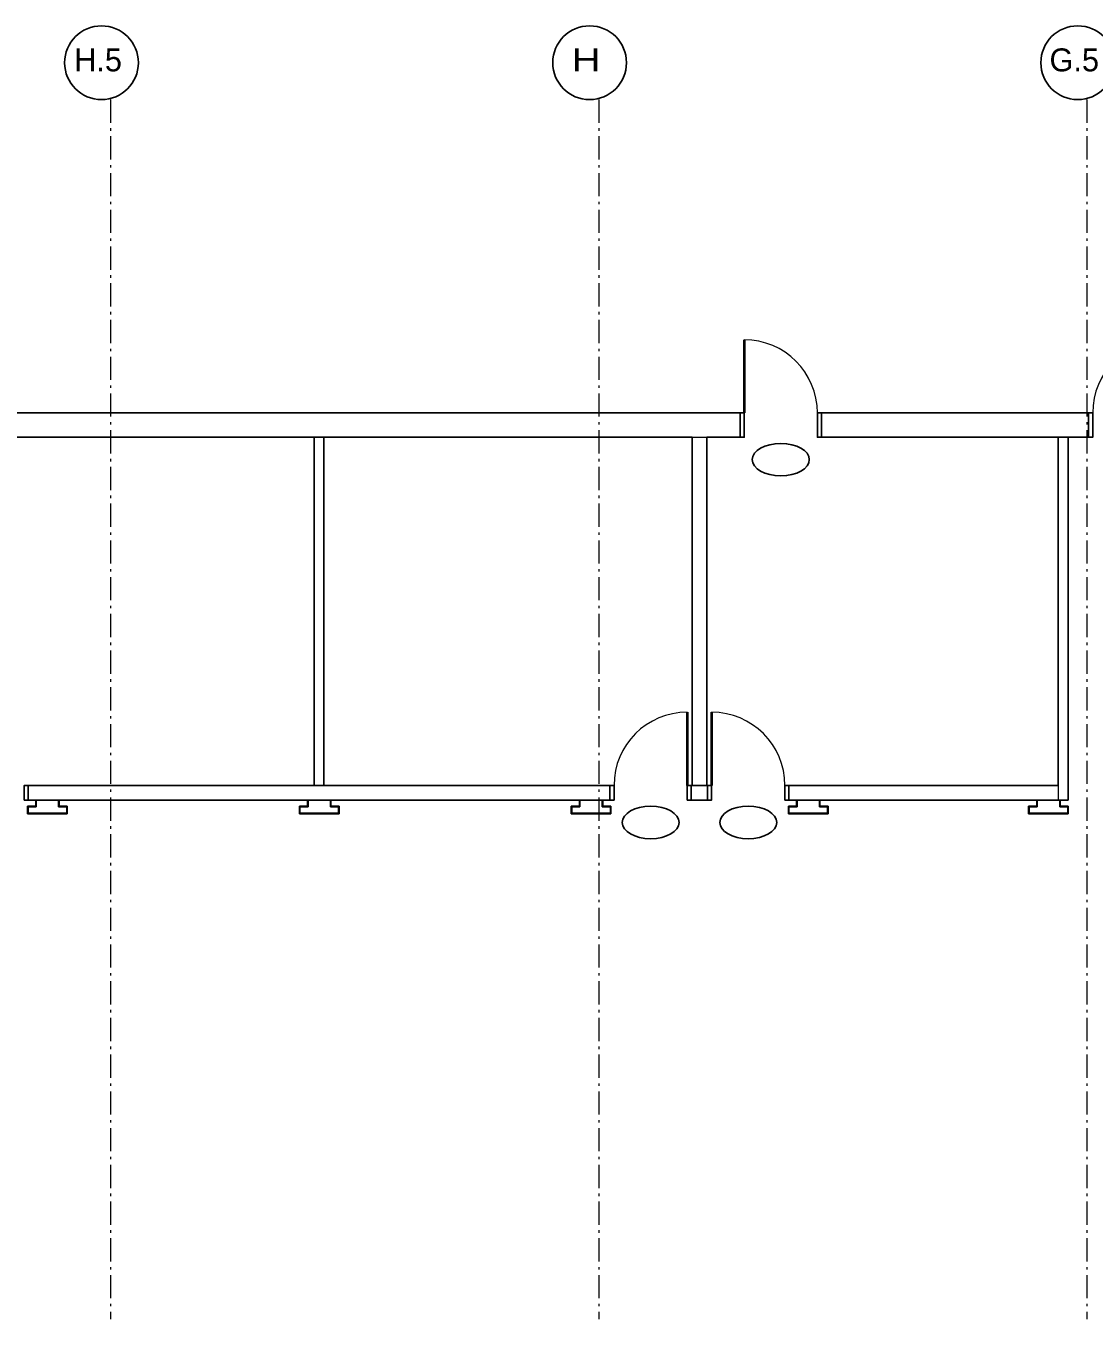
# Model space of a CAD drawing. Extents: x 10076 to 10305, y 10052 to 10157.
# Drawn here: x 10121.1 to 10164.8, y 10104.1 to 10157.1 of the extents above; entities that cross this region are included whole.
import ezdxf
from ezdxf.enums import TextEntityAlignment as Align

# ---------------------------------------------------------------- set-up
doc = ezdxf.new("R2010")
doc.units = 0
doc.header["$LTSCALE"] = 0.19
doc.linetypes.add('DOT_DASHED', pattern=[7.7, 5, -1.2, 0.3, -1.2])
for name, color, linetype, lineweight in [('1', 7, 'Continuous', 13), ('10', 7, 'DOT_DASHED', 13), ('11', 7, 'Continuous', 25), ('23', 7, 'Continuous', 25), ('25', 7, 'Continuous', 13), ('26', 7, 'Continuous', 25), ('42', 7, 'Continuous', 25)]:
    doc.layers.add(name, color=color, linetype=linetype, lineweight=lineweight)

msp = doc.modelspace()

# ---------------------------------------------------------------- linework, layer by layer
at = {"layer": '1'}
for points in [[(10108.9897, 10141.2504), (10108.9897, 10140.2504), (10150.3356, 10140.2504), (10150.3356, 10141.2504)], [(10153.669, 10141.2504), (10153.669, 10140.2504), (10164.6147, 10140.2504), (10164.6147, 10141.2504)], [(10132.8773, 10140.2504), (10132.8773, 10125.9796), (10133.2836, 10125.9796), (10133.2836, 10140.2504)], [(10148.3669, 10125.9796), (10148.3669, 10140.2504), (10148.9711, 10140.2504), (10148.9711, 10125.9796)], [(10163.3669, 10140.2504), (10163.3669, 10125.3754), (10163.7731, 10125.3754), (10163.7731, 10140.2504)], [(10121.169, 10125.9796), (10121.169, 10125.3754), (10145.0023, 10125.3754), (10145.0023, 10125.9796)], [(10148.3356, 10125.3754), (10148.3356, 10125.9796), (10149.0023, 10125.9796), (10149.0023, 10125.3754)], [(10152.3356, 10125.3754), (10152.3356, 10125.9796), (10163.3669, 10125.9796), (10163.3669, 10125.3754)], [(10121.4711, 10125.3754), (10121.4711, 10125.1254), (10121.1377, 10125.1254), (10121.1377, 10124.8129), (10122.7627, 10124.8129), (10122.7627, 10125.1254), (10122.4294, 10125.1254), (10122.4294, 10125.3754)], [(10132.6117, 10125.3754), (10132.6117, 10125.1254), (10132.2784, 10125.1254), (10132.2784, 10124.8129), (10133.9034, 10124.8129), (10133.9034, 10125.1254), (10133.57, 10125.1254), (10133.57, 10125.3754)], [(10143.7523, 10125.3754), (10143.7523, 10125.1254), (10143.419, 10125.1254), (10143.419, 10124.8129), (10145.044, 10124.8129), (10145.044, 10125.1254), (10144.7106, 10125.1254), (10144.7106, 10125.3754)], [(10152.6481, 10125.3754), (10152.6481, 10125.1254), (10152.3148, 10125.1254), (10152.3148, 10124.8129), (10153.9398, 10124.8129), (10153.9398, 10125.1254), (10153.6065, 10125.1254), (10153.6065, 10125.3754)], [(10162.4919, 10125.3754), (10162.4919, 10125.1254), (10162.1586, 10125.1254), (10162.1586, 10124.8129), (10163.7836, 10124.8129), (10163.7836, 10125.1254), (10163.4502, 10125.1254), (10163.4502, 10125.3754)]]:
    msp.add_lwpolyline(points, close=True, dxfattribs=at)
at = {"layer": '10'}
for p, q in [((10124.544, 10154.0964), (10124.544, 10104.0964)), ((10144.544, 10154.0964), (10144.544, 10104.0964)), ((10164.544, 10154.0964), (10164.544, 10104.0964))]:
    msp.add_line(p, q, dxfattribs=at)
at = {"layer": '11'}
for centre in [(10124.169, 10155.6074), (10144.169, 10155.6074), (10164.169, 10155.6074)]:
    msp.add_circle(centre, 1.511, dxfattribs=at)
at = {"layer": '23'}
for p, q in [((10108.9897, 10141.2504), (10150.3356, 10141.2504)), ((10150.3356, 10141.2504), (10150.3356, 10140.2504)), ((10153.669, 10141.2504), (10164.6147, 10141.2504)), ((10153.669, 10141.2504), (10153.669, 10140.2504)), ((10164.6147, 10141.2504), (10164.6147, 10140.2504)), ((10117.794, 10140.2504), (10132.8773, 10140.2504)), ((10132.8773, 10140.2504), (10132.8773, 10125.9796)), ((10133.2836, 10140.2504), (10133.2836, 10125.9796)), ((10133.2836, 10140.2504), (10148.3669, 10140.2504)), ((10148.3669, 10140.2504), (10148.3669, 10125.9796)), ((10148.9711, 10140.2504), (10148.9711, 10125.9796)), ((10148.9711, 10140.2504), (10150.3356, 10140.2504)), ((10153.669, 10140.2504), (10163.3669, 10140.2504)), ((10163.3669, 10140.2504), (10163.3669, 10125.9796)), ((10163.7731, 10140.2504), (10163.7731, 10125.3754)), ((10163.7731, 10140.2504), (10164.6147, 10140.2504)), ((10121.169, 10125.9796), (10132.8773, 10125.9796)), ((10121.169, 10125.9796), (10121.169, 10125.3754)), ((10133.2836, 10125.9796), (10145.0023, 10125.9796)), ((10145.0023, 10125.9796), (10145.0023, 10125.3754)), ((10148.3356, 10125.9796), (10148.3669, 10125.9796)), ((10148.3356, 10125.9796), (10148.3356, 10125.3754)), ((10148.3356, 10125.9796), (10149.0023, 10125.9796)), ((10148.9711, 10125.9796), (10149.0023, 10125.9796)), ((10149.0023, 10125.9796), (10149.0023, 10125.3754)), ((10152.3356, 10125.9796), (10152.3356, 10125.3754)), ((10152.3356, 10125.9796), (10163.3669, 10125.9796)), ((10121.4711, 10125.1254), (10121.1377, 10125.1254)), ((10121.1377, 10125.1254), (10121.1377, 10124.8129)), ((10121.4919, 10125.1046), (10121.1586, 10125.1046)), ((10121.1586, 10125.1046), (10121.1586, 10124.8337)), ((10121.169, 10125.3754), (10121.4711, 10125.3754)), ((10121.4711, 10125.3754), (10121.4711, 10125.1254)), ((10121.4919, 10125.3754), (10121.4919, 10125.1046)), ((10121.4919, 10125.3754), (10122.4086, 10125.3754)), ((10122.4086, 10125.1046), (10122.4086, 10125.3754)), ((10122.7419, 10125.1046), (10122.4086, 10125.1046)), ((10122.4294, 10125.1254), (10122.4294, 10125.3754)), ((10122.4294, 10125.3754), (10132.6117, 10125.3754)), ((10122.7627, 10125.1254), (10122.4294, 10125.1254)), ((10122.7419, 10124.8337), (10122.7419, 10125.1046)), ((10122.7627, 10124.8129), (10122.7627, 10125.1254)), ((10132.6117, 10125.1254), (10132.2784, 10125.1254)), ((10132.2784, 10125.1254), (10132.2784, 10124.8129)), ((10132.6325, 10125.1046), (10132.2992, 10125.1046)), ((10132.2992, 10125.1046), (10132.2992, 10124.8337)), ((10132.6117, 10125.3754), (10132.6117, 10125.1254)), ((10132.6325, 10125.3754), (10132.6325, 10125.1046)), ((10132.6325, 10125.3754), (10133.5492, 10125.3754)), ((10133.5492, 10125.1046), (10133.5492, 10125.3754)), ((10133.8825, 10125.1046), (10133.5492, 10125.1046)), ((10133.57, 10125.1254), (10133.57, 10125.3754)), ((10133.57, 10125.3754), (10143.7523, 10125.3754)), ((10133.9034, 10125.1254), (10133.57, 10125.1254)), ((10133.8825, 10124.8337), (10133.8825, 10125.1046)), ((10133.9034, 10124.8129), (10133.9034, 10125.1254)), ((10143.7523, 10125.1254), (10143.419, 10125.1254)), ((10143.419, 10125.1254), (10143.419, 10124.8129)), ((10143.7731, 10125.1046), (10143.4398, 10125.1046)), ((10143.4398, 10125.1046), (10143.4398, 10124.8337)), ((10143.7523, 10125.3754), (10143.7523, 10125.1254)), ((10143.7731, 10125.3754), (10143.7731, 10125.1046)), ((10143.7731, 10125.3754), (10144.6898, 10125.3754)), ((10144.6898, 10125.1046), (10144.6898, 10125.3754)), ((10145.0231, 10125.1046), (10144.6898, 10125.1046)), ((10144.7106, 10125.1254), (10144.7106, 10125.3754)), ((10144.7106, 10125.3754), (10145.0023, 10125.3754)), ((10145.044, 10125.1254), (10144.7106, 10125.1254)), ((10145.0231, 10124.8337), (10145.0231, 10125.1046)), ((10145.044, 10124.8129), (10145.044, 10125.1254)), ((10148.3356, 10125.3754), (10149.0023, 10125.3754)), ((10152.6481, 10125.1254), (10152.3148, 10125.1254)), ((10152.3148, 10125.1254), (10152.3148, 10124.8129)), ((10152.3356, 10125.3754), (10152.6481, 10125.3754)), ((10152.669, 10125.1046), (10152.3356, 10125.1046)), ((10152.3356, 10125.1046), (10152.3356, 10124.8337)), ((10152.6481, 10125.3754), (10152.6481, 10125.1254)), ((10152.669, 10125.3754), (10152.669, 10125.1046)), ((10152.669, 10125.3754), (10153.5856, 10125.3754)), ((10153.5856, 10125.1046), (10153.5856, 10125.3754)), ((10153.919, 10125.1046), (10153.5856, 10125.1046)), ((10153.6065, 10125.1254), (10153.6065, 10125.3754)), ((10153.6065, 10125.3754), (10162.4919, 10125.3754)), ((10153.9398, 10125.1254), (10153.6065, 10125.1254)), ((10153.919, 10124.8337), (10153.919, 10125.1046)), ((10153.9398, 10124.8129), (10153.9398, 10125.1254)), ((10162.4919, 10125.1254), (10162.1586, 10125.1254)), ((10162.1586, 10125.1254), (10162.1586, 10124.8129)), ((10162.5127, 10125.1046), (10162.1794, 10125.1046)), ((10162.1794, 10125.1046), (10162.1794, 10124.8337)), ((10162.4919, 10125.3754), (10162.4919, 10125.1254)), ((10162.5127, 10125.3754), (10162.5127, 10125.1046)), ((10162.5127, 10125.3754), (10163.4294, 10125.3754)), ((10163.4294, 10125.1046), (10163.4294, 10125.3754)), ((10163.7627, 10125.1046), (10163.4294, 10125.1046)), ((10163.4502, 10125.1254), (10163.4502, 10125.3754)), ((10163.4502, 10125.3754), (10163.7731, 10125.3754)), ((10163.7836, 10125.1254), (10163.4502, 10125.1254)), ((10163.7627, 10124.8337), (10163.7627, 10125.1046)), ((10163.7836, 10124.8129), (10163.7836, 10125.1254)), ((10121.1377, 10124.8129), (10122.7627, 10124.8129)), ((10121.1586, 10124.8337), (10122.7419, 10124.8337)), ((10132.2784, 10124.8129), (10133.9034, 10124.8129)), ((10132.2992, 10124.8337), (10133.8825, 10124.8337)), ((10143.419, 10124.8129), (10145.044, 10124.8129)), ((10143.4398, 10124.8337), (10145.0231, 10124.8337)), ((10152.3148, 10124.8129), (10153.9398, 10124.8129)), ((10152.3356, 10124.8337), (10153.919, 10124.8337)), ((10162.1586, 10124.8129), (10163.7836, 10124.8129)), ((10162.1794, 10124.8337), (10163.7627, 10124.8337))]:
    msp.add_line(p, q, dxfattribs=at)
at = {"layer": '25', "lineweight": 40}
for p, q in [((10150.5023, 10144.2504), (10150.5023, 10141.2504)), ((10148.169, 10128.9796), (10148.169, 10125.9796)), ((10149.169, 10128.9796), (10149.169, 10125.9796))]:
    msp.add_line(p, q, dxfattribs=at)
at = {"layer": '25'}
for centre, start, end in [((10150.5023, 10141.2504), 0.00001, 90), ((10167.7814, 10141.2504), 89.99998, 179.99998), ((10148.169, 10125.9796), 89.99998, 179.99998), ((10149.169, 10125.9796), 0.00001, 90)]:
    msp.add_arc(centre, 3, start, end, dxfattribs=at)
at = {"layer": '26'}
for points in [[(10150.3356, 10141.2504), (10150.5023, 10141.2504), (10150.5023, 10140.2504), (10150.3356, 10140.2504)], [(10153.669, 10140.2504), (10153.5023, 10140.2504), (10153.5023, 10141.2504), (10153.669, 10141.2504)], [(10164.6147, 10141.2504), (10164.7814, 10141.2504), (10164.7814, 10140.2504), (10164.6147, 10140.2504)], [(10121.169, 10125.3754), (10121.0023, 10125.3754), (10121.0023, 10125.9796), (10121.169, 10125.9796)], [(10145.0023, 10125.9796), (10145.169, 10125.9796), (10145.169, 10125.3754), (10145.0023, 10125.3754)], [(10148.3356, 10125.3754), (10148.169, 10125.3754), (10148.169, 10125.9796), (10148.3356, 10125.9796)], [(10149.0023, 10125.9796), (10149.169, 10125.9796), (10149.169, 10125.3754), (10149.0023, 10125.3754)], [(10152.3356, 10125.3754), (10152.169, 10125.3754), (10152.169, 10125.9796), (10152.3356, 10125.9796)]]:
    msp.add_lwpolyline(points, dxfattribs=at)
at = {"layer": '42'}
for centre in [(10152.0023, 10139.3337), (10146.669, 10124.4587), (10150.669, 10124.4587)]:
    msp.add_ellipse(centre, major_axis=(1.1667, 0), ratio=0.571429, dxfattribs=at)

# ---------------------------------------------------------------- texts
at = {"layer": '11'}
for s, p in [('H.5', (10124.0274, 10155.2531)), ('G.5', (10164.0274, 10155.2531))]:
    msp.add_text(s, height=0.9412, dxfattribs=at).set_placement(p, align=Align.CENTER)
at = {"layer": '11', "width": 1.3}
msp.add_text(' H ', height=0.9412, dxfattribs=at).set_placement((10144.0274, 10155.2531), align=Align.CENTER)

doc.saveas('drawing.dxf')
